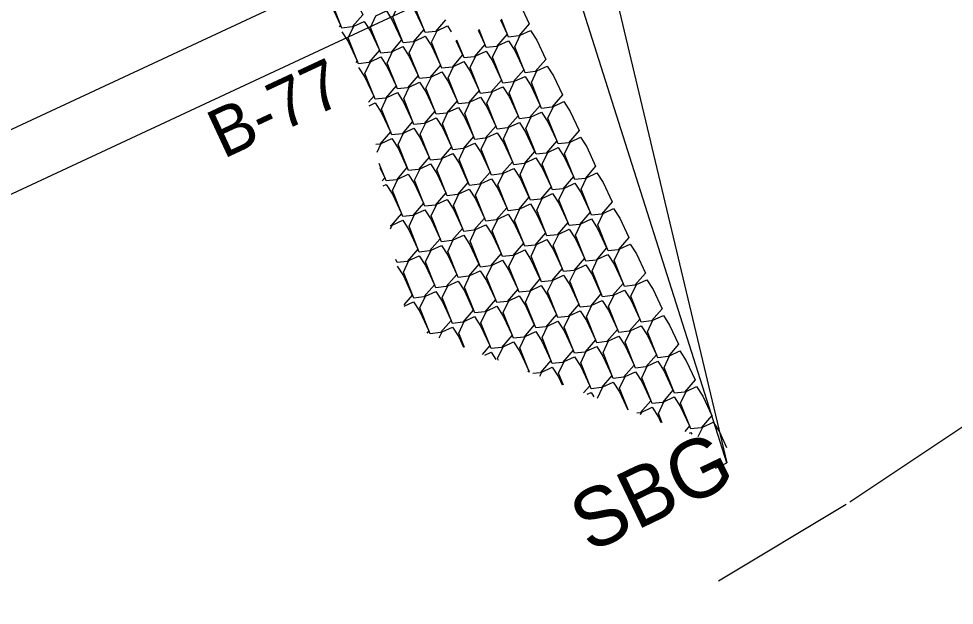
# Model space of a CAD drawing. Extents: x 2320644 to 2322941, y 921672 to 923041.
# Drawn here: x 2321755.6 to 2321851.5, y 922176.6 to 922236.7 of the extents above; entities that cross this region are included whole.
import ezdxf

# ---------------------------------------------------------------- set-up
doc = ezdxf.new("R2010")
doc.units = 0
for name, color, linetype in [('Prop Approach Slab', 7, 'Continuous'), ('Prop EOT', 7, 'Continuous'), ('Prop Horizontal Alignment Tick Large', 7, 'Continuous'), ('Sheet Profile Grid Major CELL', 7, 'Continuous'), ('Sheet Profile Grid Minor CELL', 7, 'Continuous'), ('Terminator Both', 7, 'Continuous')]:
    doc.layers.add(name, color=color, linetype=linetype)

msp = doc.modelspace()

# ---------------------------------------------------------------- linework, layer by layer
at = {"layer": 'Prop Approach Slab'}
msp.add_line((2321416.203, 922067.484), (2321809.467, 922250.794), dxfattribs=at)
at = {"layer": 'Prop Horizontal Alignment Tick Large'}
msp.add_line((2321607.894, 922150.216), (2321798.232, 922238.937), dxfattribs=at)
at = {"layer": 'Sheet Profile Grid Major CELL'}
for p, q in [((2321799.525, 922235.926), (2321799.921, 922235.313)), ((2321791.507, 922227.748), (2321792.116, 922228.032)), ((2321792.936, 922219.532), (2321793.24, 922219.674)), ((2321795.079, 922207.209), (2321796.064, 922207.668)), ((2321803.352, 922202.184), (2321804.02, 922202.495)), ((2321804.02, 922202.495), (2321804.504, 922201.745)), ((2321813.843, 922198.192), (2321814.253, 922198.383)), ((2321814.253, 922198.383), (2321814.55, 922197.923)), ((2321824.334, 922194.201), (2321824.485, 922194.271)), ((2321824.485, 922194.271), (2321824.595, 922194.101))]:
    msp.add_line(p, q, dxfattribs=at)
for points in [[(2321789.292, 922240.038), (2321789.936, 922239.042), (2321790.855, 922237.07), (2321789.769, 922235.819), (2321788.72, 922235.703), (2321787.663, 922238.355), (2321788.227, 922239.542), (2321789.292, 922240.038)], [(2321799.342, 922236.555), (2321798.301, 922235.356), (2321797.252, 922235.239), (2321796.196, 922237.891), (2321796.759, 922239.078), (2321797.824, 922239.574)], [(2321787.015, 922238.976), (2321787.659, 922237.98), (2321788.578, 922236.009), (2321788.425, 922235.833)], [(2321795.547, 922238.513), (2321796.191, 922237.516), (2321797.11, 922235.545), (2321796.024, 922234.294), (2321794.975, 922234.178), (2321793.918, 922236.83), (2321794.482, 922238.016), (2321795.547, 922238.513)], [(2321793.27, 922237.451), (2321793.914, 922236.455), (2321794.833, 922234.484), (2321793.747, 922233.233), (2321792.698, 922233.116), (2321791.641, 922235.768), (2321792.205, 922236.955), (2321793.27, 922237.451)], [(2321807.233, 922237.616), (2321807.919, 922236.143), (2321806.834, 922234.892), (2321805.785, 922234.775), (2321805.057, 922236.602)], [(2321790.993, 922236.39), (2321791.636, 922235.393), (2321792.555, 922233.422), (2321791.47, 922232.171), (2321790.421, 922232.055), (2321789.364, 922234.707), (2321789.928, 922235.893), (2321790.993, 922236.39)], [(2321804.956, 922236.554), (2321805.642, 922235.081), (2321804.556, 922233.831), (2321803.507, 922233.714), (2321802.78, 922235.54)], [(2321800.401, 922234.431), (2321801.088, 922232.958), (2321800.002, 922231.708), (2321798.953, 922231.591), (2321797.896, 922234.243), (2321798.46, 922235.43), (2321799.525, 922235.926)], [(2321802.678, 922235.493), (2321803.365, 922234.02), (2321802.279, 922232.769), (2321801.23, 922232.653), (2321800.502, 922234.479)], [(2321808.057, 922235.462), (2321808.701, 922234.466), (2321809.62, 922232.495), (2321808.534, 922231.244), (2321807.485, 922231.127), (2321806.428, 922233.779), (2321806.992, 922234.966), (2321808.057, 922235.462)], [(2321788.715, 922235.328), (2321789.359, 922234.332), (2321790.278, 922232.361), (2321790.125, 922232.185)], [(2321797.248, 922234.865), (2321797.891, 922233.868), (2321798.81, 922231.897), (2321797.725, 922230.646), (2321796.676, 922230.53), (2321795.619, 922233.181), (2321796.183, 922234.368), (2321797.248, 922234.865)], [(2321794.97, 922233.803), (2321795.614, 922232.807), (2321796.533, 922230.835), (2321795.447, 922229.585), (2321794.398, 922229.468), (2321793.342, 922232.12), (2321793.905, 922233.307), (2321794.97, 922233.803)], [(2321805.78, 922234.401), (2321806.424, 922233.405), (2321807.343, 922231.433), (2321806.257, 922230.182), (2321805.208, 922230.066), (2321804.151, 922232.718), (2321804.715, 922233.905), (2321805.78, 922234.401)], [(2321792.693, 922232.742), (2321793.337, 922231.745), (2321794.256, 922229.774), (2321793.17, 922228.523), (2321792.121, 922228.407), (2321791.064, 922231.058), (2321791.628, 922232.245), (2321792.693, 922232.742)], [(2321803.503, 922233.339), (2321804.146, 922232.343), (2321805.065, 922230.372), (2321803.98, 922229.121), (2321802.931, 922229.004), (2321801.874, 922231.656), (2321802.438, 922232.843), (2321803.503, 922233.339)], [(2321790.416, 922231.68), (2321791.06, 922230.684), (2321791.979, 922228.712), (2321791.446, 922228.099)], [(2321801.225, 922232.278), (2321801.869, 922231.282), (2321802.788, 922229.31), (2321801.702, 922228.059), (2321800.653, 922227.943), (2321799.597, 922230.595), (2321800.16, 922231.782), (2321801.225, 922232.278)], [(2321809.758, 922231.814), (2321810.401, 922230.818), (2321811.32, 922228.847), (2321810.235, 922227.596), (2321809.186, 922227.479), (2321808.129, 922230.131), (2321808.693, 922231.318), (2321809.758, 922231.814)], [(2321798.948, 922231.216), (2321799.592, 922230.22), (2321800.511, 922228.249), (2321799.425, 922226.998), (2321798.376, 922226.881), (2321797.319, 922229.533), (2321797.883, 922230.72), (2321798.948, 922231.216)], [(2321807.48, 922230.753), (2321808.124, 922229.756), (2321809.043, 922227.785), (2321807.957, 922226.534), (2321806.908, 922226.418), (2321805.852, 922229.07), (2321806.415, 922230.256), (2321807.48, 922230.753)], [(2321796.671, 922230.155), (2321797.315, 922229.159), (2321798.234, 922227.187), (2321797.148, 922225.936), (2321796.099, 922225.82), (2321795.042, 922228.472), (2321795.606, 922229.659), (2321796.671, 922230.155)], [(2321805.203, 922229.691), (2321805.847, 922228.695), (2321806.766, 922226.724), (2321805.68, 922225.473), (2321804.631, 922225.356), (2321803.574, 922228.008), (2321804.138, 922229.195), (2321805.203, 922229.691)], [(2321794.394, 922229.094), (2321795.037, 922228.097), (2321795.956, 922226.126), (2321794.871, 922224.875), (2321793.822, 922224.758), (2321792.765, 922227.41), (2321793.329, 922228.597), (2321794.394, 922229.094)], [(2321792.116, 922228.032), (2321792.76, 922227.036), (2321793.679, 922225.064), (2321792.593, 922223.814), (2321792.199, 922223.77)], [(2321802.926, 922228.63), (2321803.57, 922227.633), (2321804.489, 922225.662), (2321803.403, 922224.411), (2321802.354, 922224.295), (2321801.297, 922226.947), (2321801.861, 922228.133), (2321802.926, 922228.63)], [(2321811.458, 922228.166), (2321812.102, 922227.17), (2321813.021, 922225.198), (2321811.935, 922223.948), (2321810.886, 922223.831), (2321809.829, 922226.483), (2321810.393, 922227.67), (2321811.458, 922228.166)], [(2321800.649, 922227.568), (2321801.292, 922226.572), (2321802.211, 922224.601), (2321801.126, 922223.35), (2321800.077, 922223.233), (2321799.02, 922225.885), (2321799.584, 922227.072), (2321800.649, 922227.568)], [(2321809.181, 922227.105), (2321809.825, 922226.108), (2321810.744, 922224.137), (2321809.658, 922222.886), (2321808.609, 922222.77), (2321807.552, 922225.421), (2321808.116, 922226.608), (2321809.181, 922227.105)], [(2321798.371, 922226.507), (2321799.015, 922225.511), (2321799.934, 922223.539), (2321798.848, 922222.288), (2321797.799, 922222.172), (2321796.743, 922224.824), (2321797.306, 922226.01), (2321798.371, 922226.507)], [(2321806.904, 922226.043), (2321807.547, 922225.047), (2321808.466, 922223.075), (2321807.381, 922221.825), (2321806.332, 922221.708), (2321805.275, 922224.36), (2321805.839, 922225.547), (2321806.904, 922226.043)], [(2321796.094, 922225.445), (2321796.738, 922224.449), (2321797.657, 922222.478), (2321796.571, 922221.227), (2321795.522, 922221.11), (2321794.465, 922223.762), (2321795.029, 922224.949), (2321796.094, 922225.445)], [(2321804.626, 922224.982), (2321805.27, 922223.985), (2321806.189, 922222.014), (2321805.103, 922220.763), (2321804.054, 922220.647), (2321802.998, 922223.298), (2321803.561, 922224.485), (2321804.626, 922224.982)], [(2321792.332, 922223.004), (2321792.752, 922223.887), (2321793.817, 922224.384)], [(2321793.817, 922224.384), (2321794.461, 922223.388), (2321795.379, 922221.416), (2321794.294, 922220.165), (2321793.245, 922220.049), (2321792.538, 922221.823)], [(2321802.349, 922223.92), (2321802.993, 922222.924), (2321803.912, 922220.952), (2321802.826, 922219.702), (2321801.777, 922219.585), (2321800.72, 922222.237), (2321801.284, 922223.424), (2321802.349, 922223.92)], [(2321813.159, 922224.518), (2321813.802, 922223.522), (2321814.721, 922221.55), (2321813.636, 922220.299), (2321812.587, 922220.183), (2321811.53, 922222.835), (2321812.094, 922224.022), (2321813.159, 922224.518)], [(2321810.881, 922223.456), (2321811.525, 922222.46), (2321812.444, 922220.489), (2321811.358, 922219.238), (2321810.309, 922219.121), (2321809.253, 922221.773), (2321809.816, 922222.96), (2321810.881, 922223.456)], [(2321800.072, 922222.859), (2321800.716, 922221.862), (2321801.634, 922219.891), (2321800.549, 922218.64), (2321799.5, 922218.524), (2321798.443, 922221.175), (2321799.007, 922222.362), (2321800.072, 922222.859)], [(2321808.604, 922222.395), (2321809.248, 922221.399), (2321810.167, 922219.427), (2321809.081, 922218.177), (2321808.032, 922218.06), (2321806.975, 922220.712), (2321807.539, 922221.899), (2321808.604, 922222.395)], [(2321792.609, 922221.413), (2321793.102, 922220.355), (2321792.845, 922220.058)], [(2321797.795, 922221.797), (2321798.438, 922220.801), (2321799.357, 922218.83), (2321798.272, 922217.579), (2321797.223, 922217.462), (2321796.166, 922220.114), (2321796.73, 922221.301), (2321797.795, 922221.797)], [(2321806.327, 922221.334), (2321806.971, 922220.337), (2321807.889, 922218.366), (2321806.804, 922217.115), (2321805.755, 922216.998), (2321804.698, 922219.65), (2321805.262, 922220.837), (2321806.327, 922221.334)], [(2321795.517, 922220.736), (2321796.161, 922219.739), (2321797.08, 922217.768), (2321795.994, 922216.517), (2321794.945, 922216.401), (2321793.889, 922219.052), (2321794.452, 922220.239), (2321795.517, 922220.736)], [(2321804.05, 922220.272), (2321804.693, 922219.276), (2321805.612, 922217.304), (2321804.527, 922216.054), (2321803.478, 922215.937), (2321802.421, 922218.589), (2321802.985, 922219.776), (2321804.05, 922220.272)], [(2321814.859, 922220.87), (2321815.503, 922219.873), (2321816.422, 922217.902), (2321815.336, 922216.651), (2321814.287, 922216.535), (2321813.23, 922219.187), (2321813.794, 922220.373), (2321814.859, 922220.87)], [(2321793.24, 922219.674), (2321793.884, 922218.678), (2321794.803, 922216.707), (2321793.717, 922215.456), (2321793.646, 922215.448)], [(2321801.772, 922219.211), (2321802.416, 922218.214), (2321803.335, 922216.243), (2321802.249, 922214.992), (2321801.2, 922214.875), (2321800.144, 922217.527), (2321800.707, 922218.714), (2321801.772, 922219.211)], [(2321812.582, 922219.808), (2321813.226, 922218.812), (2321814.144, 922216.841), (2321813.059, 922215.59), (2321812.01, 922215.473), (2321810.953, 922218.125), (2321811.517, 922219.312), (2321812.582, 922219.808)], [(2321799.495, 922218.149), (2321800.139, 922217.153), (2321801.058, 922215.181), (2321799.972, 922213.931), (2321798.923, 922213.814), (2321797.866, 922216.466), (2321798.43, 922217.653), (2321799.495, 922218.149)], [(2321810.305, 922218.747), (2321810.948, 922217.751), (2321811.867, 922215.779), (2321810.782, 922214.528), (2321809.733, 922214.412), (2321808.676, 922217.064), (2321809.24, 922218.25), (2321810.305, 922218.747)], [(2321808.027, 922217.685), (2321808.671, 922216.689), (2321809.59, 922214.718), (2321808.504, 922213.467), (2321807.455, 922213.35), (2321806.399, 922216.002), (2321806.962, 922217.189), (2321808.027, 922217.685)], [(2321816.56, 922217.222), (2321817.203, 922216.225), (2321818.122, 922214.254), (2321817.037, 922213.003), (2321815.988, 922212.887), (2321814.931, 922215.538), (2321815.495, 922216.725), (2321816.56, 922217.222)], [(2321797.218, 922217.088), (2321797.862, 922216.091), (2321798.78, 922214.12), (2321797.695, 922212.869), (2321796.646, 922212.753), (2321795.589, 922215.404), (2321796.153, 922216.591), (2321797.218, 922217.088)], [(2321805.75, 922216.624), (2321806.394, 922215.628), (2321807.313, 922213.656), (2321806.227, 922212.405), (2321805.178, 922212.289), (2321804.121, 922214.941), (2321804.685, 922216.127), (2321805.75, 922216.624)], [(2321793.697, 922215.154), (2321793.876, 922215.53), (2321794.941, 922216.026)], [(2321794.941, 922216.026), (2321795.584, 922215.03), (2321796.503, 922213.058), (2321795.417, 922211.808), (2321794.369, 922211.691), (2321794.246, 922211.999)], [(2321803.473, 922215.562), (2321804.117, 922214.566), (2321805.035, 922212.595), (2321803.95, 922211.344), (2321802.901, 922211.227), (2321801.844, 922213.879), (2321802.408, 922215.066), (2321803.473, 922215.562)], [(2321814.282, 922216.16), (2321814.926, 922215.164), (2321815.845, 922213.192), (2321814.759, 922211.942), (2321813.71, 922211.825), (2321812.654, 922214.477), (2321813.217, 922215.664), (2321814.282, 922216.16)], [(2321801.196, 922214.501), (2321801.839, 922213.505), (2321802.758, 922211.533), (2321801.672, 922210.282), (2321800.624, 922210.166), (2321799.567, 922212.818), (2321800.131, 922214.005), (2321801.196, 922214.501)], [(2321812.005, 922215.099), (2321812.649, 922214.102), (2321813.568, 922212.131), (2321812.482, 922210.88), (2321811.433, 922210.764), (2321810.376, 922213.415), (2321810.94, 922214.602), (2321812.005, 922215.099)], [(2321798.918, 922213.439), (2321799.562, 922212.443), (2321800.481, 922210.472), (2321799.395, 922209.221), (2321798.346, 922209.104), (2321797.289, 922211.756), (2321797.853, 922212.943), (2321798.918, 922213.439)], [(2321809.728, 922214.037), (2321810.372, 922213.041), (2321811.29, 922211.07), (2321810.205, 922209.819), (2321809.156, 922209.702), (2321808.099, 922212.354), (2321808.663, 922213.541), (2321809.728, 922214.037)], [(2321818.26, 922213.574), (2321818.904, 922212.577), (2321819.823, 922210.606), (2321818.737, 922209.355), (2321817.688, 922209.238), (2321816.631, 922211.89), (2321817.195, 922213.077), (2321818.26, 922213.574)], [(2321796.641, 922212.378), (2321797.285, 922211.382), (2321798.204, 922209.41), (2321797.118, 922208.159), (2321796.069, 922208.043), (2321795.012, 922210.695), (2321795.576, 922211.882), (2321796.641, 922212.378)], [(2321807.451, 922212.976), (2321808.094, 922211.979), (2321809.013, 922210.008), (2321807.927, 922208.757), (2321806.879, 922208.641), (2321805.822, 922211.292), (2321806.386, 922212.479), (2321807.451, 922212.976)], [(2321815.983, 922212.512), (2321816.627, 922211.516), (2321817.545, 922209.544), (2321816.46, 922208.294), (2321815.411, 922208.177), (2321814.354, 922210.829), (2321814.918, 922212.016), (2321815.983, 922212.512)], [(2321805.173, 922211.914), (2321805.817, 922210.918), (2321806.736, 922208.947), (2321805.65, 922207.696), (2321804.601, 922207.579), (2321803.544, 922210.231), (2321804.108, 922211.418), (2321805.173, 922211.914)], [(2321813.706, 922211.451), (2321814.349, 922210.454), (2321815.268, 922208.483), (2321814.182, 922207.232), (2321813.134, 922207.115), (2321812.077, 922209.767), (2321812.641, 922210.954), (2321813.706, 922211.451)], [(2321794.365, 922211.315), (2321795.008, 922210.32), (2321795.926, 922208.349), (2321795.055, 922207.345)], [(2321802.896, 922210.853), (2321803.54, 922209.856), (2321804.459, 922207.885), (2321803.373, 922206.634), (2321802.324, 922206.518), (2321801.267, 922209.17), (2321801.831, 922210.356), (2321802.896, 922210.853)], [(2321800.619, 922209.791), (2321801.263, 922208.795), (2321802.181, 922206.824), (2321801.096, 922205.573), (2321800.047, 922205.456), (2321798.99, 922208.108), (2321799.554, 922209.295), (2321800.619, 922209.791)], [(2321811.428, 922210.389), (2321812.072, 922209.393), (2321812.991, 922207.421), (2321811.905, 922206.171), (2321810.856, 922206.054), (2321809.799, 922208.706), (2321810.363, 922209.893), (2321811.428, 922210.389)], [(2321819.961, 922209.925), (2321820.604, 922208.929), (2321821.523, 922206.958), (2321820.437, 922205.707), (2321819.389, 922205.59), (2321818.332, 922208.242), (2321818.896, 922209.429), (2321819.961, 922209.925)], [(2321798.342, 922208.73), (2321798.985, 922207.733), (2321799.904, 922205.762), (2321798.818, 922204.511), (2321797.769, 922204.395), (2321796.713, 922207.047), (2321797.277, 922208.233), (2321798.342, 922208.73)], [(2321809.151, 922209.328), (2321809.795, 922208.331), (2321810.714, 922206.36), (2321809.628, 922205.109), (2321808.579, 922204.993), (2321807.522, 922207.644), (2321808.086, 922208.831), (2321809.151, 922209.328)], [(2321817.683, 922208.864), (2321818.327, 922207.868), (2321819.246, 922205.896), (2321818.16, 922204.645), (2321817.111, 922204.529), (2321816.054, 922207.181), (2321816.618, 922208.367), (2321817.683, 922208.864)], [(2321796.064, 922207.668), (2321796.708, 922206.672), (2321797.627, 922204.701), (2321797.406, 922204.446)], [(2321806.874, 922208.266), (2321807.518, 922207.27), (2321808.436, 922205.298), (2321807.351, 922204.048), (2321806.302, 922203.931), (2321805.245, 922206.583), (2321805.809, 922207.77), (2321806.874, 922208.266)], [(2321815.406, 922207.802), (2321816.05, 922206.806), (2321816.969, 922204.835), (2321815.883, 922203.584), (2321814.834, 922203.467), (2321813.777, 922206.119), (2321814.341, 922207.306), (2321815.406, 922207.802)], [(2321804.597, 922207.205), (2321805.24, 922206.208), (2321806.159, 922204.237), (2321805.073, 922202.986), (2321804.024, 922202.87), (2321802.968, 922205.521), (2321803.532, 922206.708), (2321804.597, 922207.205)], [(2321813.129, 922206.741), (2321813.773, 922205.745), (2321814.691, 922203.773), (2321813.606, 922202.522), (2321812.557, 922202.406), (2321811.5, 922205.058), (2321812.064, 922206.245), (2321813.129, 922206.741)], [(2321801.284, 922202.97), (2321800.69, 922204.46), (2321801.254, 922205.647), (2321802.319, 922206.143)], [(2321802.319, 922206.143), (2321802.963, 922205.147), (2321803.882, 922203.175), (2321803.103, 922202.278)], [(2321810.852, 922205.679), (2321811.495, 922204.683), (2321812.414, 922202.712), (2321811.328, 922201.461), (2321810.279, 922201.344), (2321809.223, 922203.996), (2321809.787, 922205.183), (2321810.852, 922205.679)], [(2321821.661, 922206.277), (2321822.305, 922205.281), (2321823.224, 922203.31), (2321822.138, 922202.059), (2321821.089, 922201.942), (2321820.032, 922204.594), (2321820.596, 922205.781), (2321821.661, 922206.277)], [(2321798.68, 922203.961), (2321798.977, 922204.585), (2321800.042, 922205.082)], [(2321800.042, 922205.082), (2321800.686, 922204.085), (2321801.189, 922203.006)], [(2321819.384, 922205.216), (2321820.028, 922204.219), (2321820.946, 922202.248), (2321819.861, 922200.997), (2321818.812, 922200.881), (2321817.755, 922203.532), (2321818.319, 922204.719), (2321819.384, 922205.216)], [(2321807.941, 922200.438), (2321806.945, 922202.935), (2321807.509, 922204.122), (2321808.574, 922204.618)], [(2321808.574, 922204.618), (2321809.218, 922203.622), (2321810.137, 922201.65), (2321809.051, 922200.399), (2321808.269, 922200.313)], [(2321817.107, 922204.154), (2321817.75, 922203.158), (2321818.669, 922201.187), (2321817.583, 922199.936), (2321816.534, 922199.819), (2321815.478, 922202.471), (2321816.042, 922203.658), (2321817.107, 922204.154)], [(2321804.758, 922201.649), (2321804.668, 922201.873), (2321805.232, 922203.06), (2321806.297, 922203.556)], [(2321806.297, 922203.556), (2321806.941, 922202.56), (2321807.86, 922200.589), (2321807.781, 922200.498)], [(2321814.829, 922203.093), (2321815.473, 922202.096), (2321816.392, 922200.125), (2321815.306, 922198.874), (2321814.257, 922198.758), (2321813.2, 922201.41), (2321813.764, 922202.596), (2321814.829, 922203.093)], [(2321811.414, 922199.116), (2321810.923, 922200.348), (2321811.487, 922201.535), (2321812.552, 922202.031)], [(2321812.552, 922202.031), (2321813.196, 922201.035), (2321814.115, 922199.064), (2321813.478, 922198.331)], [(2321823.362, 922202.629), (2321824.005, 922201.633), (2321824.924, 922199.661), (2321823.838, 922198.411), (2321822.789, 922198.294), (2321821.733, 922200.946), (2321822.297, 922202.133), (2321823.362, 922202.629)], [(2321809.001, 922200.034), (2321809.21, 922200.473), (2321810.275, 922200.97)], [(2321810.275, 922200.97), (2321810.918, 922199.973), (2321811.297, 922199.16)], [(2321821.084, 922201.568), (2321821.728, 922200.571), (2321822.647, 922198.6), (2321821.561, 922197.349), (2321820.512, 922197.233), (2321819.455, 922199.884), (2321820.019, 922201.071), (2321821.084, 922201.568)], [(2321818.071, 922196.583), (2321817.178, 922198.823), (2321817.742, 922200.01), (2321818.807, 922200.506)], [(2321818.807, 922200.506), (2321819.451, 922199.51), (2321820.37, 922197.538), (2321819.284, 922196.288), (2321818.947, 922196.25)], [(2321814.912, 922197.785), (2321815.465, 922198.948), (2321816.53, 922199.445)], [(2321816.53, 922199.445), (2321817.173, 922198.448), (2321818.037, 922196.596)], [(2321825.062, 922198.981), (2321825.706, 922197.985), (2321826.625, 922196.013), (2321825.539, 922194.762), (2321824.49, 922194.646), (2321823.433, 922197.298), (2321823.997, 922198.485), (2321825.062, 922198.981)], [(2321821.544, 922195.262), (2321821.156, 922196.236), (2321821.72, 922197.423), (2321822.785, 922197.919)], [(2321822.785, 922197.919), (2321823.429, 922196.923), (2321824.347, 922194.952), (2321823.854, 922194.383)], [(2321819.322, 922196.107), (2321819.443, 922196.362), (2321820.508, 922196.858)], [(2321820.508, 922196.858), (2321821.151, 922195.862), (2321821.406, 922195.314)], [(2321825.233, 922193.858), (2321825.698, 922194.836), (2321826.763, 922195.333)], [(2321826.763, 922195.333), (2321827.406, 922194.336), (2321828.146, 922192.75)]]:
    msp.add_lwpolyline(points, dxfattribs=at)
at = {"layer": 'Sheet Profile Grid Minor CELL'}
for p, q in [((2321828.171, 922191.155), (2321800.436, 922278.589)), ((2321814.871, 922247.099), (2321828.171, 922191.155)), ((2321827.014, 922190.616), (2321828.171, 922191.155))]:
    msp.add_line(p, q, dxfattribs=at)
at = {"layer": 'Terminator Both'}
for p, q in [((2321840.773, 922187.192), (2321856.613, 922197.739)), ((2321827.317, 922179.081), (2321840.387, 922186.947))]:
    msp.add_line(p, q, dxfattribs=at)

# ---------------------------------------------------------------- texts
at = {"layer": 'Prop EOT'}
msp.add_text('B-77', height=5, rotation=25.01869, dxfattribs=at).set_placement((2321776.546, 922222.26))
at = {"layer": 'Sheet Profile Grid Minor CELL'}
msp.add_text('SBG', height=6, rotation=25.71648, dxfattribs=at).set_placement((2321814.086, 922181.904))

doc.saveas('drawing.dxf')
